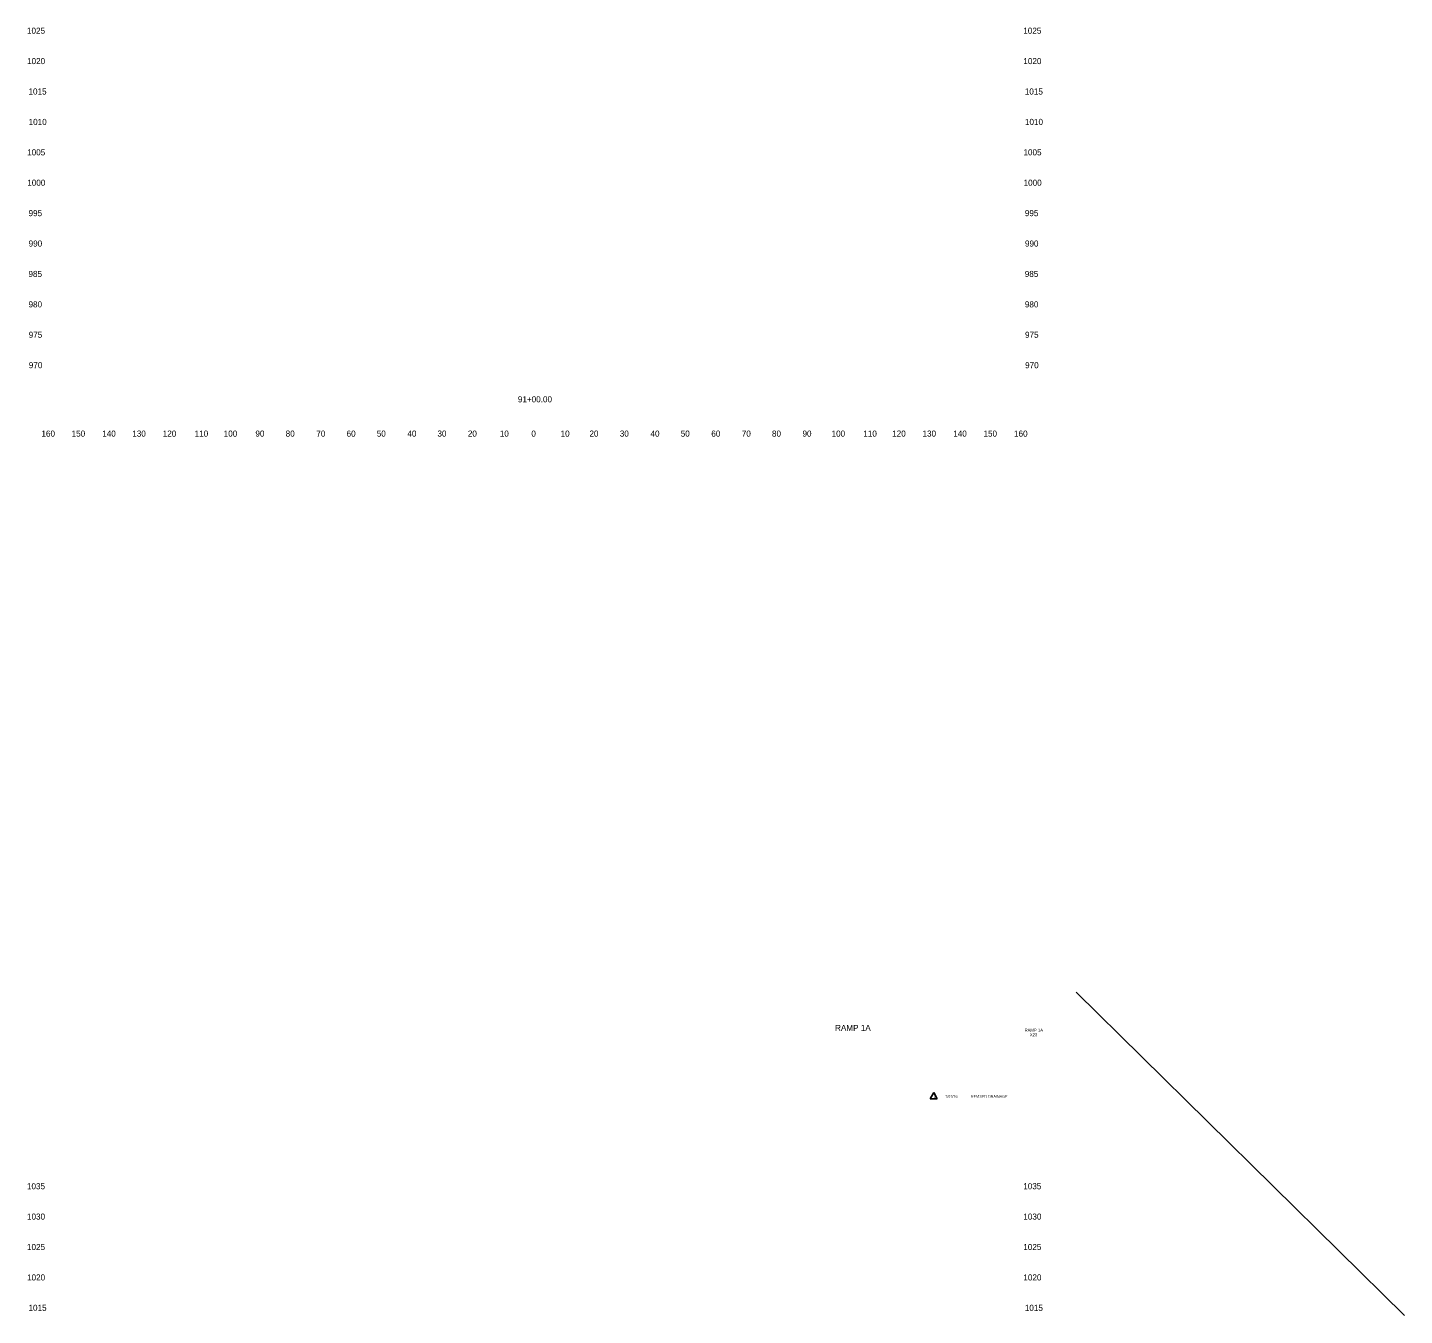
# Model space of a CAD drawing. Extents: x 4994 to 6873, y 4997 to 8804.
# Drawn here: x 6023.5 to 6476.6, y 5908.5 to 6332 of the extents above; entities that cross this region are included whole.
import ezdxf

# ---------------------------------------------------------------- set-up
doc = ezdxf.new("R2010")
doc.units = 0
for name, color, linetype in [('RD_SHT_ID', 7, 'Continuous'), ('RD_SHT_TX', 7, 'Continuous'), ('RD_XS_TX_Offset', 7, 'Continuous'), ('RD_XS_TX_Station', 7, 'Continuous')]:
    doc.layers.add(name, color=color, linetype=linetype)

msp = doc.modelspace()

# ---------------------------------------------------------------- linework, layer by layer
at = {"layer": 'RD_SHT_ID'}
msp.add_line((6368.54, 6014.81), (6476.55, 5908.5), dxfattribs=at)
at = {"layer": 'RD_SHT_TX'}
for p, q in [((6321.67, 5981.8), (6320.53, 5979.77)), ((6321.67, 5981.8), (6322.81, 5979.77)), ((6320.53, 5979.77), (6322.81, 5979.77))]:
    msp.add_line(p, q, dxfattribs=at)

# ---------------------------------------------------------------- texts
at = {"layer": 'RD_SHT_ID'}
for s, height, p in [('RAMP 1A', 2, (6289.21, 6002.06)), ('RAMP 1A', 1, (6351.57, 6001.8)), ('X23', 1, (6353.29, 6000.3))]:
    msp.add_text(s, height=height, dxfattribs=at).set_placement(p)
at = {"layer": 'RD_SHT_TX'}
for s, p in [('1', (6321.67, 5980.1)), ('7/07/16', (6325.45, 5980.06)), ('REVISED DRAINAGE', (6333.9, 5980.06))]:
    msp.add_text(s, height=0.88, dxfattribs=at).set_placement(p)
at = {"layer": 'RD_XS_TX_Offset'}
for s, p in [('1025', (6023.34, 6330)), ('1025', (6351.14, 6330)), ('1020', (6023.37, 6320)), ('1020', (6351.17, 6320)), ('1015', (6023.85, 6310)), ('1015', (6351.65, 6310)), ('1010', (6023.88, 6300)), ('1010', (6351.68, 6300)), ('1005', (6023.4, 6290)), ('1005', (6351.2, 6290)), ('1000', (6023.44, 6280)), ('1000', (6351.24, 6280)), ('995', (6023.86, 6270)), ('995', (6351.66, 6270)), ('990', (6023.89, 6260)), ('990', (6351.69, 6260)), ('985', (6023.83, 6250)), ('985', (6351.63, 6250)), ('980', (6023.86, 6240)), ('980', (6351.66, 6240)), ('975', (6023.91, 6230)), ('975', (6351.71, 6230)), ('970', (6023.94, 6220)), ('970', (6351.74, 6220)), ('160', (6028.1, 6197.5)), ('150', (6038.04, 6197.5)), ('140', (6048.1, 6197.5)), ('130', (6057.99, 6197.5)), ('120', (6068.01, 6197.5)), ('110', (6078.51, 6197.5)), ('100', (6088.07, 6197.5)), ('90', (6098.5, 6197.5)), ('80', (6108.46, 6197.5)), ('70', (6118.54, 6197.5)), ('60', (6128.5, 6197.5)), ('50', (6138.43, 6197.5)), ('40', (6148.5, 6197.5)), ('30', (6158.39, 6197.5)), ('20', (6168.4, 6197.5)), ('10', (6178.91, 6197.5)), ('0', (6189.3, 6197.5)), ('0', (6189.3, 6197.5)), ('10', (6198.91, 6197.5)), ('20', (6208.4, 6197.5)), ('30', (6218.39, 6197.5)), ('40', (6228.5, 6197.5)), ('50', (6238.43, 6197.5)), ('60', (6248.5, 6197.5)), ('70', (6258.54, 6197.5)), ('80', (6268.46, 6197.5)), ('90', (6278.5, 6197.5)), ('100', (6288.07, 6197.5)), ('110', (6298.51, 6197.5)), ('120', (6308.01, 6197.5)), ('130', (6317.99, 6197.5)), ('140', (6328.1, 6197.5)), ('150', (6338.04, 6197.5)), ('160', (6348.1, 6197.5)), ('1035', (6023.33, 5950)), ('1035', (6351.13, 5950)), ('1030', (6023.36, 5940)), ('1030', (6351.16, 5940)), ('1025', (6023.34, 5930)), ('1025', (6351.14, 5930)), ('1020', (6023.37, 5920)), ('1020', (6351.17, 5920)), ('1015', (6023.85, 5910)), ('1015', (6351.65, 5910))]:
    msp.add_text(s, height=2, dxfattribs=at).set_placement(p)
at = {"layer": 'RD_XS_TX_Station'}
msp.add_text('91+00.00', height=2, dxfattribs=at).set_placement((6184.86, 6208.78))

doc.saveas('drawing.dxf')
